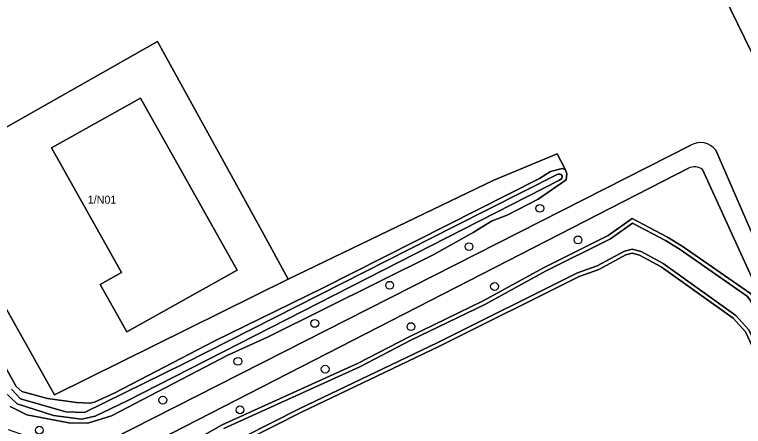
# Model space of a CAD drawing. Extents: x 162788 to 163838, y 385791 to 386523.
# Drawn here: x 163321.5 to 163412.6, y 386420.1 to 386471.6 of the extents above; entities that cross this region are included whole.
import ezdxf

# ---------------------------------------------------------------- set-up
doc = ezdxf.new("R2010")
doc.units = 0
for name, color, linetype in [('IMGEO_Boom', 7, 'Continuous'), ('IMGEO_Erf', 7, 'Continuous'), ('IMGEO_Grasland_overig', 7, 'Continuous'), ('IMGEO_Groenvoorziening', 7, 'Continuous'), ('IMGEO_Hek', 7, 'Continuous'), ('IMGEO_Loofbos', 7, 'Continuous'), ('IMGEO_Oever', 7, 'Continuous'), ('IMGEO_Pand', 7, 'Continuous'), ('IMGEO_Pand_nummerreeks', 7, 'Continuous'), ('IMGEO_Voetpad_halfverhard', 7, 'Continuous'), ('IMGEO_Waterloop', 7, 'Continuous')]:
    doc.layers.add(name, color=color, linetype=linetype)

msp = doc.modelspace()

# ---------------------------------------------------------------- linework, layer by layer
at = {"layer": 'IMGEO_Boom'}
for centre in [(163387.164, 386447.336), (163378.317, 386442.544), (163391.941, 386443.386), (163368.404, 386437.714), (163381.509, 386437.558), (163359.049, 386432.941), (163371.065, 386432.543), (163349.439, 386428.191), (163360.346, 386427.219), (163340.059, 386423.342), (163349.7, 386422.124), (163324.621, 386419.58)]:
    msp.add_circle(centre, 0.489, dxfattribs=at)
at = {"layer": 'IMGEO_Erf'}
for points in [[(163339.386, 386468.21), (163310.756, 386451.993), (163317.42, 386440.156), (163326.502, 386424.021), (163355.739, 386438.49), (163352.415, 386444.532)], [(163326.145, 386454.892), (163337.265, 386461.127), (163349.337, 386439.596), (163335.563, 386431.874), (163332.236, 386437.808), (163334.89, 386439.295)]]:
    msp.add_lwpolyline(points, close=True, dxfattribs=at)
at = {"layer": 'IMGEO_Grasland_overig'}
msp.add_lwpolyline([(163310.95, 386444.424), (163321.739, 386425.062), (163322.439, 386424.422), (163325.658, 386423.56), (163329.276, 386423.038), (163330.935, 386422.978), (163331.515, 386423.097), (163334.075, 386424.276), (163346.493, 386430.727), (163359.991, 386437.358), (163387.127, 386451.059), (163388.507, 386451.958), (163389.947, 386452.317), (163390.396, 386452.147), (163389.323, 386454.145), (163381.408, 386450.859), (163369.402, 386445.074), (163355.739, 386438.49), (163326.502, 386424.021), (163317.42, 386440.156)], dxfattribs=at)
at = {"layer": 'IMGEO_Groenvoorziening'}
for points in [[(163409.774, 386487.164), (163403.388, 386487.947), (163421.295, 386451.142), (163442.645, 386407.261), (163447.662, 386411.875), (163448.879, 386413.338), (163450.146, 386416.054), (163446.214, 386422.129), (163423.585, 386464.146)], [(163405.753, 386452.344), (163334.672, 386415.878), (163383.512, 386402.536), (163396.906, 386398.67)], [(163422.166, 386420.051), (163407.513, 386452.183)], [(163343.355, 386417.901), (163347.46, 386420.256), (163364.468, 386427.948), (163370.84, 386431.281), (163380.074, 386435.751), (163387.631, 386439.905), (163395.725, 386443.946), (163398.697, 386446.045), (163403.105, 386443.749), (163404.972, 386442.611), (163413.482, 386436.662), (163415.999, 386433.033), (163417.676, 386427.836), (163421.189, 386420.42), (163422.129, 386417.678)]]:
    msp.add_lwpolyline(points, dxfattribs=at)
msp.add_arc((163406.513, 386450.95), 1.588, 50.9622, 118.58437, dxfattribs=at)
at = {"layer": 'IMGEO_Hek'}
for points in [[(163310.756, 386451.993), (163339.386, 386468.21), (163352.415, 386444.532), (163355.739, 386438.49)], [(163355.739, 386438.49), (163369.402, 386445.074), (163381.408, 386450.859), (163389.323, 386454.145), (163390.396, 386452.147)], [(163310.756, 386451.993), (163317.42, 386440.156), (163326.502, 386424.021), (163355.739, 386438.49)]]:
    msp.add_lwpolyline(points, dxfattribs=at)
at = {"layer": 'IMGEO_Loofbos'}
for points in [[(163442.645, 386407.261), (163421.295, 386451.142), (163403.388, 386487.947), (163400.855, 386488.258), (163361.92, 386489.569), (163343.653, 386490.184), (163343.048, 386490.514), (163342.818, 386490.69), (163342.57, 386490.879), (163342.345, 386491.332), (163342.457, 386491.84)], [(163310.756, 386451.993), (163339.386, 386468.21), (163352.415, 386444.532), (163355.739, 386438.49), (163369.402, 386445.074), (163381.408, 386450.859), (163389.323, 386454.145), (163390.396, 386452.147), (163390.526, 386451.637), (163390.466, 386450.917), (163386.946, 386448.478), (163383.166, 386446.542), (163381.127, 386445.743), (163378.847, 386444.306), (163373.928, 386441.57), (163353.211, 386431.263), (163348.192, 386428.966), (163333.654, 386421.397), (163330.675, 386420.459), (163328.296, 386420.5), (163323.058, 386421.522), (163320.999, 386422.563)], [(163320.718, 386419.684), (163322.857, 386418.903), (163330.897, 386417.041), (163406.028, 386455.229)], [(163409.149, 386454.612), (163423.605, 386421.349), (163435.813, 386397.111), (163440.049, 386389.072), (163447.742, 386373.253), (163456.374, 386356.495), (163466.085, 386337.115), (163467.723, 386333.437)], [(163419.604, 386415.487), (163414.891, 386427.593), (163412.851, 386431.872), (163411.336, 386433.577), (163402.314, 386440.029), (163399.634, 386441.468), (163398.713, 386441.719), (163397.923, 386441.526), (163394.544, 386439.679), (163392.076, 386438.818), (163374.544, 386430.043), (163357.388, 386421.856), (163350.39, 386418.291)]]:
    msp.add_lwpolyline(points, dxfattribs=at)
msp.add_arc((163407.256, 386453.239), 2.338, 35.95196, 121.68247, dxfattribs=at)
at = {"layer": 'IMGEO_Oever'}
for points in [[(163320.999, 386422.563), (163323.058, 386421.522), (163328.296, 386420.5), (163330.675, 386420.459), (163333.654, 386421.397), (163348.192, 386428.966), (163353.211, 386431.263), (163373.928, 386441.57), (163378.847, 386444.306), (163381.127, 386445.743), (163383.166, 386446.542), (163386.946, 386448.478), (163390.466, 386450.917), (163390.526, 386451.637), (163390.396, 386452.147), (163389.947, 386452.317), (163388.507, 386451.958), (163387.127, 386451.059), (163359.991, 386437.358), (163346.493, 386430.727), (163334.075, 386424.276), (163331.515, 386423.097), (163330.935, 386422.978), (163329.276, 386423.038), (163325.658, 386423.56), (163322.439, 386424.422), (163321.739, 386425.062), (163310.95, 386444.424)], [(163321.152, 386424.725), (163322.268, 386423.517), (163327.942, 386421.891), (163330.268, 386421.798), (163342.711, 386427.911), (163376.563, 386445.094), (163389.412, 386451.6), (163389.586, 386451.618), (163389.746, 386451.601), (163389.831, 386451.559), (163389.962, 386451.37), (163389.979, 386451.264), (163389.904, 386451.08), (163389.628, 386450.857), (163335.532, 386423.194), (163331.596, 386421.316), (163329.892, 386420.964), (163326.396, 386421.404), (163321.872, 386422.872), (163320.256, 386424.398)], [(163422.129, 386417.678), (163421.189, 386420.42), (163417.676, 386427.836), (163415.999, 386433.033), (163413.482, 386436.662), (163404.972, 386442.611), (163403.105, 386443.749), (163398.697, 386446.045), (163395.725, 386443.946), (163387.631, 386439.905), (163380.074, 386435.751), (163370.84, 386431.281), (163364.468, 386427.948), (163347.46, 386420.256), (163343.355, 386417.901)], [(163347.688, 386419.81), (163364.687, 386427.498), (163371.065, 386430.834), (163380.304, 386435.307), (163387.863, 386439.462), (163395.982, 386443.516), (163398.736, 386445.461), (163402.859, 386443.313), (163404.698, 386442.192), (163413.122, 386436.303), (163415.546, 386432.809), (163417.21, 386427.651), (163420.725, 386420.231), (163421.664, 386417.492)], [(163420.084, 386415.633), (163415.35, 386427.792), (163413.272, 386432.151), (163411.673, 386433.951), (163402.579, 386440.454), (163399.82, 386441.935), (163398.72, 386442.235), (163397.741, 386441.996), (163394.34, 386440.138), (163391.881, 386439.28), (163374.324, 386430.492), (163357.167, 386422.304), (163350.187, 386418.749)], [(163350.39, 386418.291), (163357.388, 386421.856), (163374.544, 386430.043), (163392.076, 386438.818), (163394.544, 386439.679), (163397.923, 386441.526), (163398.713, 386441.719), (163399.634, 386441.468), (163402.314, 386440.029), (163411.336, 386433.577), (163412.851, 386431.872), (163414.891, 386427.593), (163419.604, 386415.487)]]:
    msp.add_lwpolyline(points, dxfattribs=at)
at = {"layer": 'IMGEO_Pand'}
msp.add_lwpolyline([(163349.337, 386439.596), (163337.265, 386461.127), (163326.145, 386454.892), (163334.89, 386439.295), (163332.236, 386437.808), (163335.563, 386431.874)], close=True, dxfattribs=at)
at = {"layer": 'IMGEO_Voetpad_halfverhard'}
for points in [[(163406.028, 386455.229), (163330.897, 386417.041), (163334.672, 386415.878), (163405.753, 386452.344)], [(163424.343, 386414.621), (163427.12, 386408.931), (163427.599, 386407.892), (163428.538, 386406.551), (163431.795, 386400.112), (163445.403, 386373.774), (163452.356, 386359.815), (163452.496, 386359.375), (163452.396, 386358.815), (163456.374, 386356.495), (163447.742, 386373.253), (163440.049, 386389.072), (163435.813, 386397.111), (163423.605, 386421.349), (163409.149, 386454.612)], [(163407.513, 386452.183), (163422.166, 386420.051)]]:
    msp.add_lwpolyline(points, dxfattribs=at)
for centre, radius, start, end in [((163407.256, 386453.239), 2.338, 35.95196, 121.68247), ((163406.513, 386450.95), 1.588, 50.9622, 118.58437)]:
    msp.add_arc(centre, radius, start, end, dxfattribs=at)
at = {"layer": 'IMGEO_Waterloop'}
for points in [[(163320.256, 386424.398), (163321.872, 386422.872), (163326.396, 386421.404), (163329.892, 386420.964), (163331.596, 386421.316), (163335.532, 386423.194), (163389.628, 386450.857), (163389.904, 386451.08), (163389.979, 386451.264), (163389.962, 386451.37), (163389.831, 386451.559), (163389.746, 386451.601), (163389.586, 386451.618), (163389.412, 386451.6), (163376.563, 386445.094), (163342.711, 386427.911), (163330.268, 386421.798), (163327.942, 386421.891), (163322.268, 386423.517), (163321.152, 386424.725)], [(163421.664, 386417.492), (163420.725, 386420.231), (163417.21, 386427.651), (163415.546, 386432.809), (163413.122, 386436.303), (163404.698, 386442.192), (163402.859, 386443.313), (163398.736, 386445.461), (163395.982, 386443.516), (163387.863, 386439.462), (163380.304, 386435.307), (163371.065, 386430.834), (163364.687, 386427.498), (163347.688, 386419.81)], [(163350.187, 386418.749), (163357.167, 386422.304), (163374.324, 386430.492), (163391.881, 386439.28), (163394.34, 386440.138), (163397.741, 386441.996), (163398.72, 386442.235), (163399.82, 386441.935), (163402.579, 386440.454), (163411.673, 386433.951), (163413.272, 386432.151), (163415.35, 386427.792), (163420.084, 386415.633)]]:
    msp.add_lwpolyline(points, dxfattribs=at)

# ---------------------------------------------------------------- texts
at = {"layer": 'IMGEO_Pand_nummerreeks'}
msp.add_text('1/N01', height=1, dxfattribs=at).set_placement((163330.676, 386447.919))

doc.saveas('drawing.dxf')
